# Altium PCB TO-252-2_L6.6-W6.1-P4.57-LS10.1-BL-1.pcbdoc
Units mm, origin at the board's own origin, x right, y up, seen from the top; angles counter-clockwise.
Board outline 19.83 x 24.03 mm, 2 copper layers (Top Layer, Bottom Layer), stack 0 mm thick; 1 components, 0 nets, 3 pads, 0 vias.
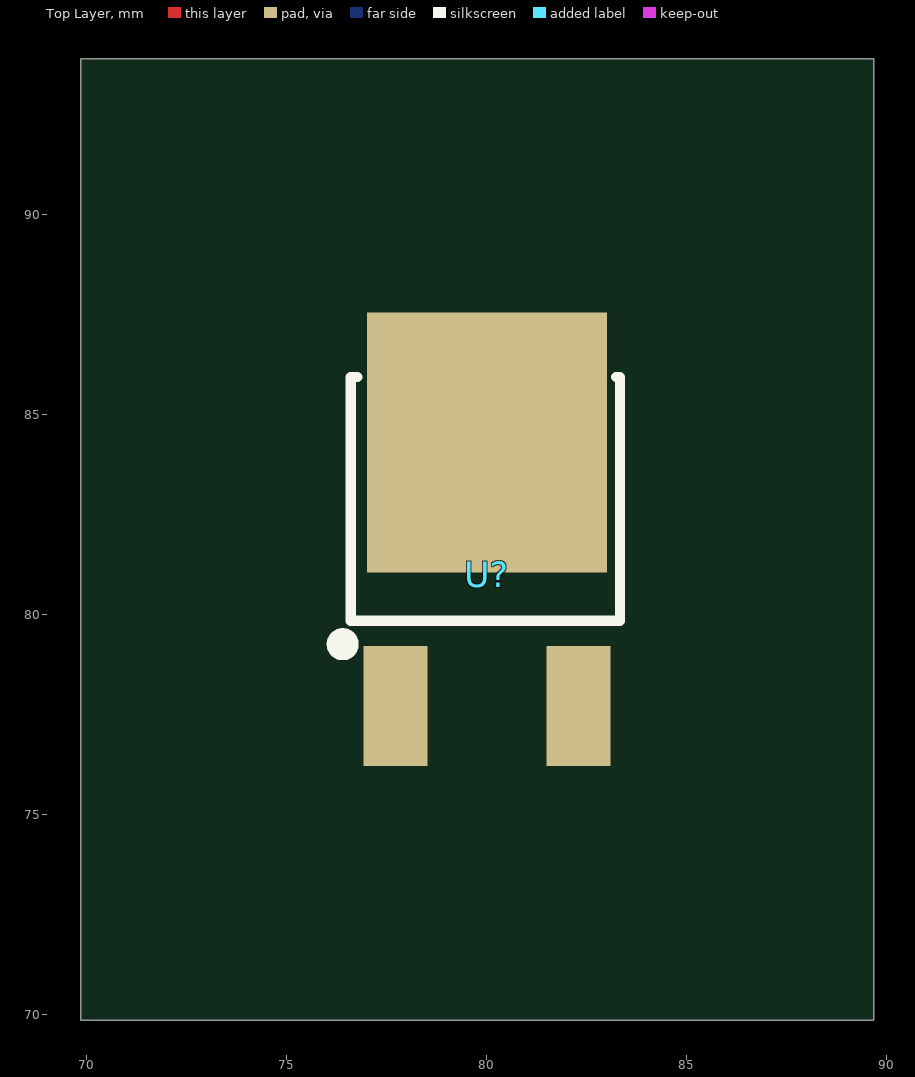
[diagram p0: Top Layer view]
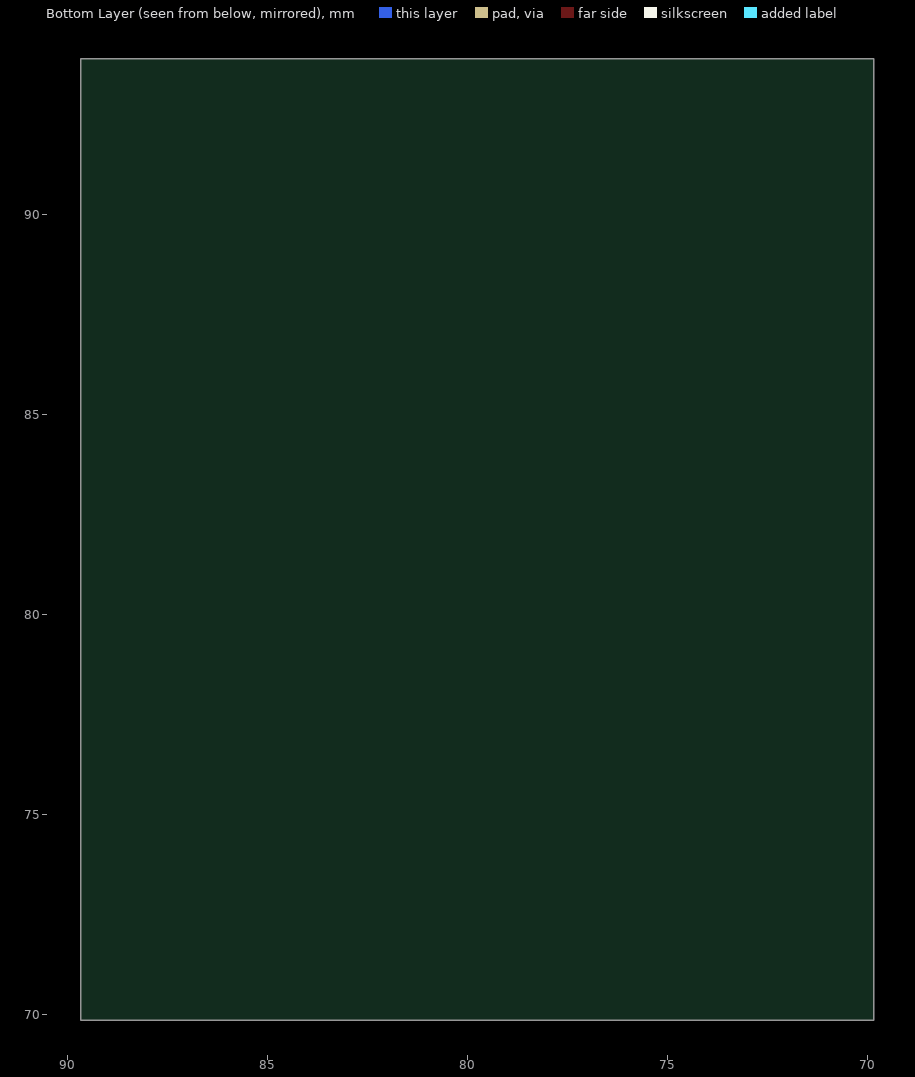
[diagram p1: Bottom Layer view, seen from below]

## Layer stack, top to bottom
Top Layer: signal copper (thickness not stored)
Bottom Layer: signal copper (thickness not stored)

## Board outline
89.681,69.85 69.85,69.85 69.85,93.884 89.681,93.884

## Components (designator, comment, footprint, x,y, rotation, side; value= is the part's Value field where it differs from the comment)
U? "" TO-252-2_L6.6-W6.1-P4.57-LS10.1-BL-1 80.004,80.992 r0 top

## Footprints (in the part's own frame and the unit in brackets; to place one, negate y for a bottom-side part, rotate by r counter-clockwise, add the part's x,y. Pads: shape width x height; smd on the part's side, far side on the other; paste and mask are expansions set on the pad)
TO-252-2_L6.6-W6.1-P4.57-LS10.1-BL-1 [mm]
  rect 1.6x3 smd: 1(-2.285,-3.292) 3(2.285,-3.286)
  rect 6x6.5 smd: 2(0,3.292)
  silkscreen extent -3.8,-1.95 3.33,4.94

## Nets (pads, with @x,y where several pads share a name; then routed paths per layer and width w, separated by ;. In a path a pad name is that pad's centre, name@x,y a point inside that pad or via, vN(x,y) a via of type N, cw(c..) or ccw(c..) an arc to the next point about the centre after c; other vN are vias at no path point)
pads on no net: U?.1 U?.2 U?.3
